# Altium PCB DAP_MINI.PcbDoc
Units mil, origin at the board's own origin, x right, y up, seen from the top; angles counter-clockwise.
Board outline 1574.69 x 695 mil, 2 copper layers (Top Layer, Bottom Layer), stack 61.756 mil thick; 34 components, 48 nets, 171 pads, 93 vias.
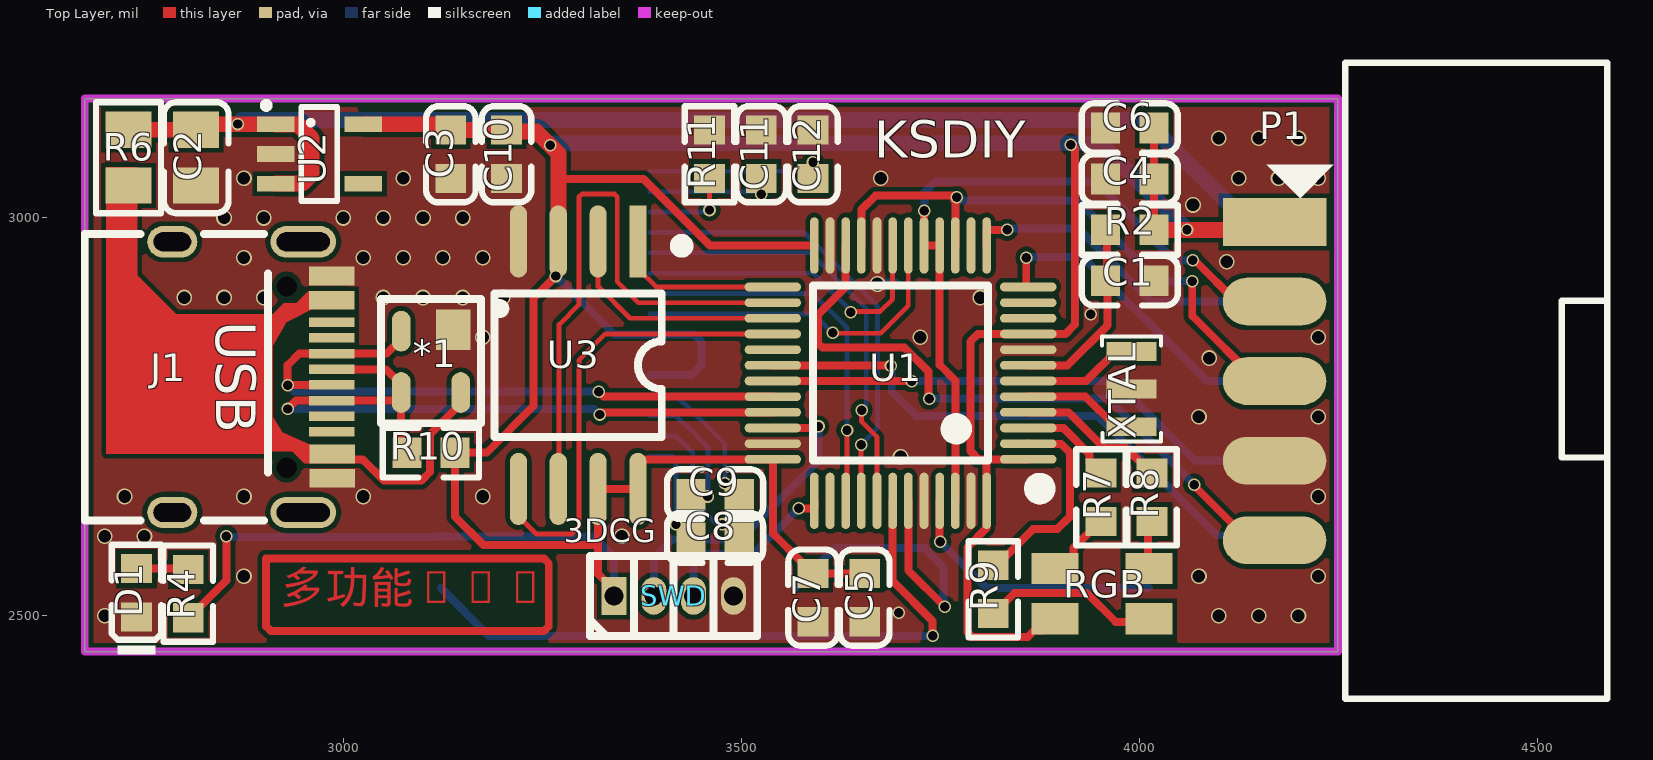
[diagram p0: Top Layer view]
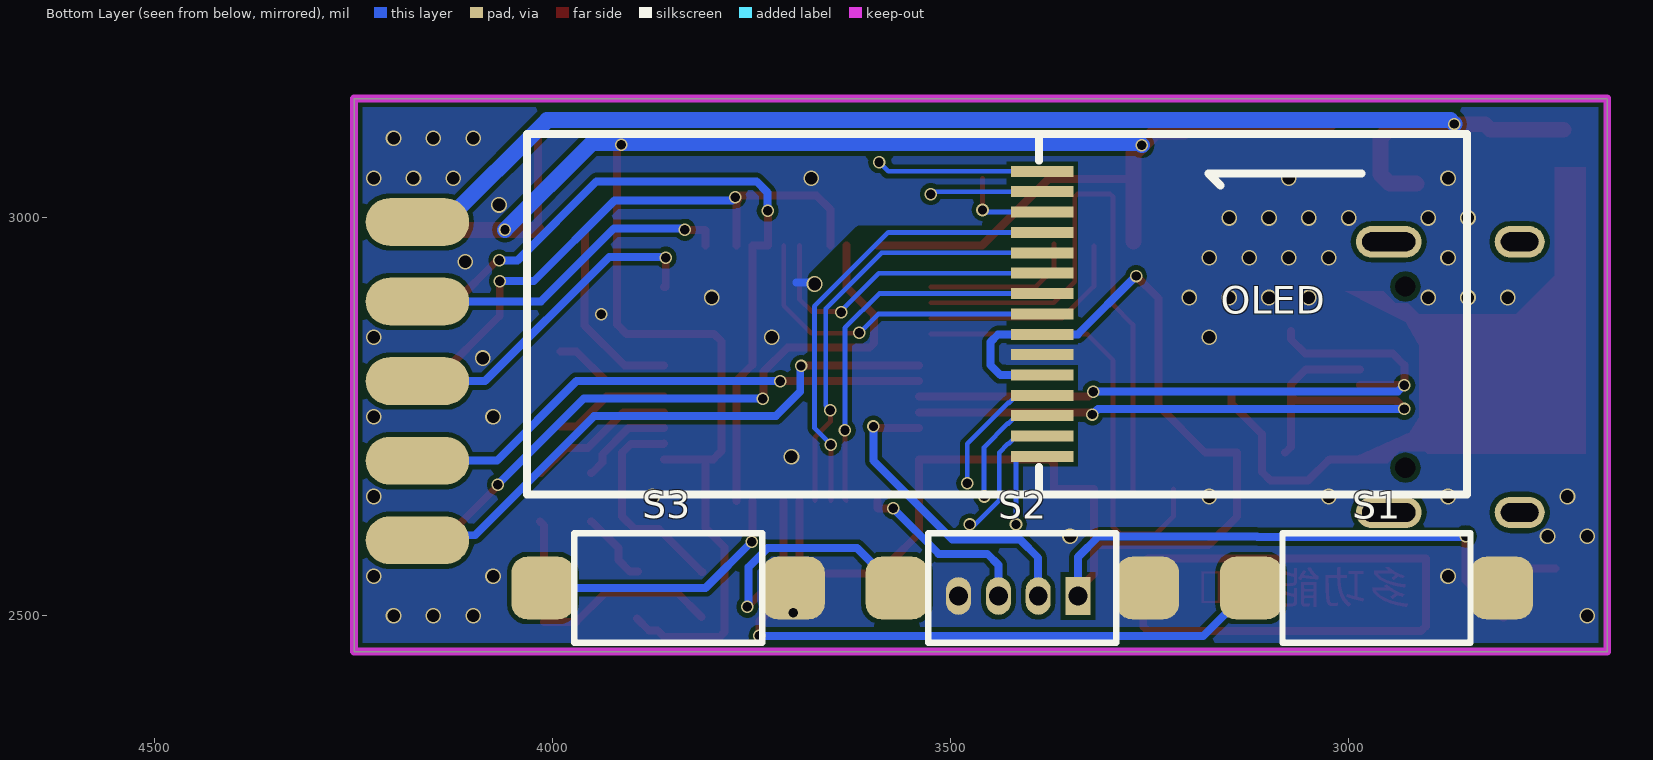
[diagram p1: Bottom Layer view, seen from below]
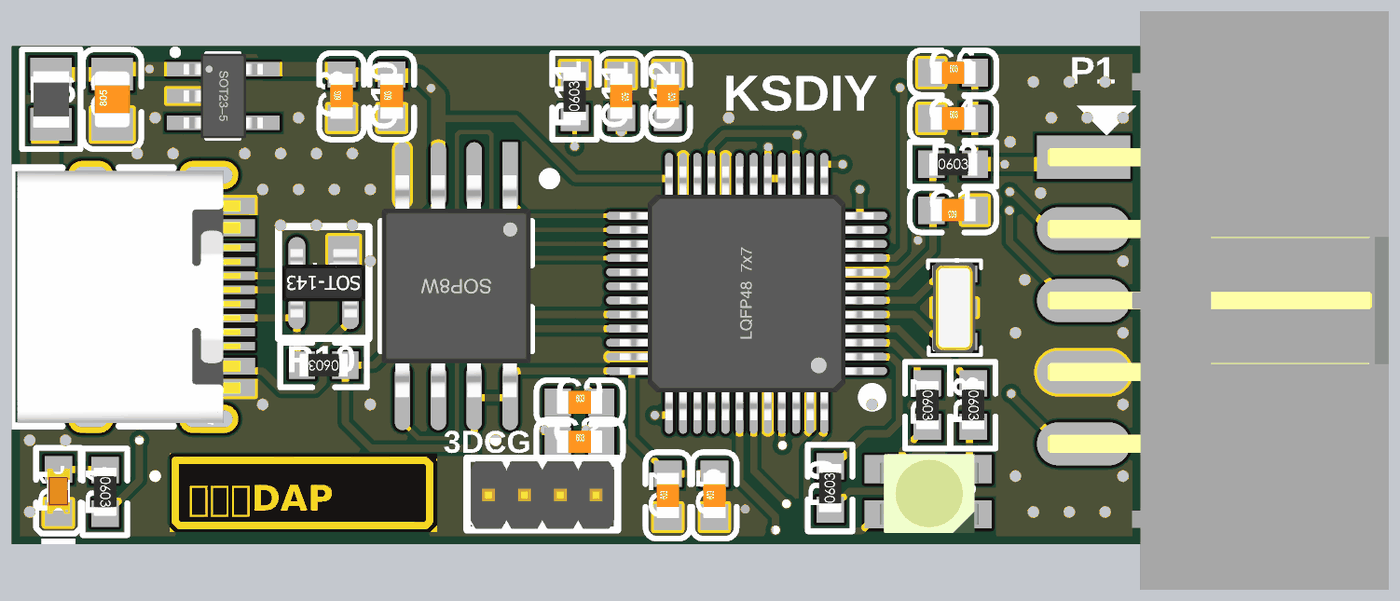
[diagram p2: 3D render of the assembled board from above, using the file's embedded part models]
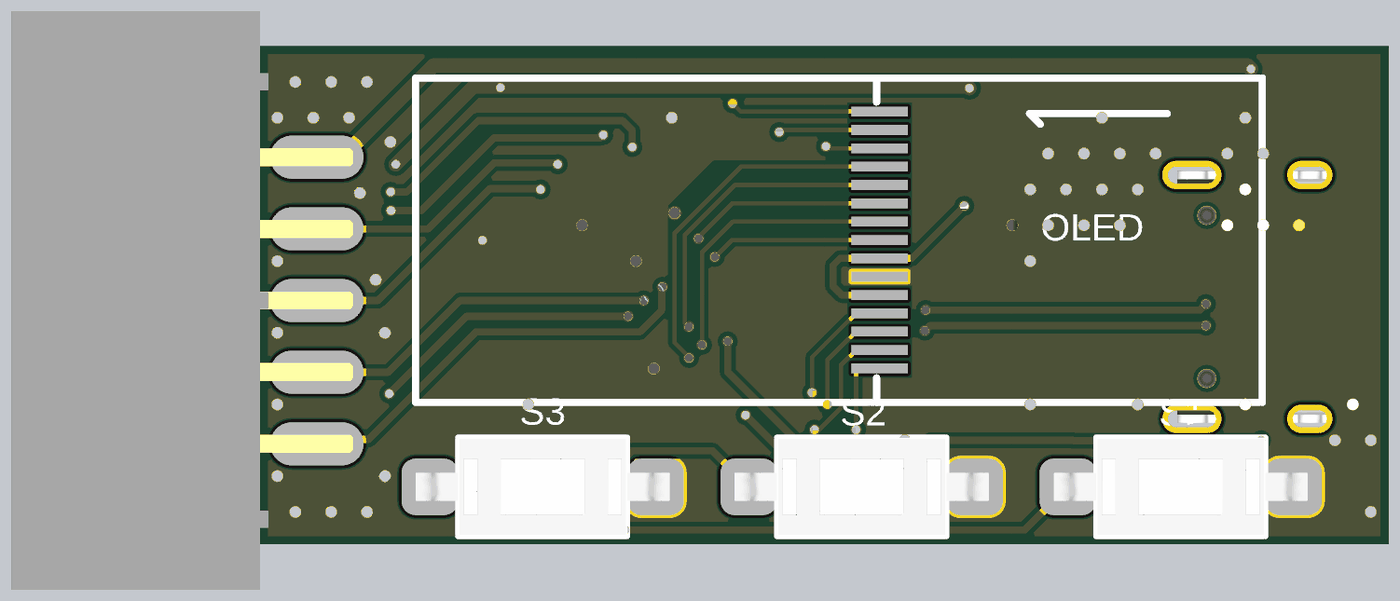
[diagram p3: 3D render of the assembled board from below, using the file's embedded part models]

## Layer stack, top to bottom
Top Solder: solder mask 1, SM-001, Dk 4
Top Layer: signal copper 1.378
Dielectric 1: core 59, Core-043, Dk 4.3
Bottom Layer: signal copper 1.378
Bottom Solder: solder mask 1, SM-001, Dk 4

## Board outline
2675,2455 2675,3150 4249.69,3150 4249.69,2455

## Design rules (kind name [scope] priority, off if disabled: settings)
Clearance [All] p1: gap=6 ignorepadtopadclearanceinfootprint=FALSE
PolygonConnect [All] p1: connectstyle=Direct reliefconductorwidth=10 reliefentries=4 polygonreliefangle="90 Angle" airgapwidth=10
RoutingVias [All] p1: holewidth=11.81 width=15.75 viastyle="Through Hole" minholewidth=11.81 minwidth=15.75 maxholewidth=11.81 maxwidth=15.75
SolderMaskExpansion [All] p1: expansion=4 istentingtop=FALSE
Width [InNet('No Net')] p1: maxlimit=20 minlimit=6 preferedwidth=6
30 further rules are at their usual default settings.

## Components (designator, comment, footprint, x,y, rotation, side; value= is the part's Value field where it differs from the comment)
*1 "PRTR5V0U2X" LC-SOT-143 3110,2820 r90 top
C1 "106" 0603_C 3988,2921 r180 top
C2 "106" 0805_C 2815,3075.75 r90 top
C3 "106" 0603_C 3135,3080 r90 top value=104
C4 "106" 0603_C 3988,3049 r0 top value=104
C5 "106" 0603_C 3655,2523 r90 top value=104
C6 "106" 0603_C 3988,3113 r0 top value=104
C7 "106" 0603_C 3590,2523 r90 top value=104
C8 "106" 0603_C 3467,2598 r0 top value=104
C9 "106" 0603_C 3467,2653 r0 top value=104
C10 "106" 0603_C 3205,3080 r90 top
C11 "106" 0603_C 3525,3080 r270 top value=104
C12 "106" 0603_C 3590,3080 r270 top value=104
D1 "白灯 0603" 0603_LED_S1 2740,2529 r90 top
J1 "USB type C" "USB Type-C-16Pin_A" 2785,2800 r270 top
OLED "QG-2832TLBFG02" 0.91-OLED 4031.57,3156.38 r180 bottom (schematic designator OLED1)
P1 "Header 5X2" "300S-2*5P 2.54MM_2" 4170,2995 r0 top
R2 "Res2" 0603_R 3988,2985 r0 top value=10K
R4 "Res2" 0603_R 2805,2528 r270 top value=1K
R6 "1A保险丝" 0805_L 2730,3075.75 r270 top value=1000MA
R7 "1K" 0603_R 3952,2649 r270 top value=300R
R8 "1K" 0603_R 4016,2649 r270 top value=300R
R9 "1K" 0603_R 3816.46,2533.36 r90 top value=300R
R10 "Res2" LC-0603_R 3110,2705 r180 top value=1.5K
R11 "Res2" 0603_R 3460,3080 r90 top value=10K
RGB "RGB_LED" LED_3528_RGB 3953.02,2528.08 r180 top (schematic designator RGB1)
S1 "RST" KEY 2965,2535 r0 bottom
S2 "RST" KEY 3410,2535 r0 bottom
S3 "RST" KEY 3855,2535 r0 bottom
SWD "Header 4" HDR1.27-LI-4P 3415,2525 r0 top (schematic designator SWD1)
U1 "STM32F103C" "LQFP48 7X7_N" 3700,2805 r90 top
U2 "MIC5219" SOT23-5N 2970,3080.37 r270 top
U3 "W25QXX" SOP8W_N 3295,2815 r270 top
XTAL "8M" XTAL-3215-3P 3990,2785 r90 top (schematic designator XTAL1)

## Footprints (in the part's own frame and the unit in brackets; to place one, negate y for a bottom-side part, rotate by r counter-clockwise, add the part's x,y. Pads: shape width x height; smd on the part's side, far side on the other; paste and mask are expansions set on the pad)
0.91-OLED [mm]
  rect 2x0.35 smd: 1(16.423,-11.585) 2(16.423,-10.933) 3(16.423,-10.283) 4(16.423,-9.633) 5(16.423,-8.985) 6(16.423,-8.335) 7(16.423,-7.685) 8(16.423,-7.035) 9(16.423,-6.385) 10(16.423,-5.735) 11(16.423,-5.085) 12(16.423,-4.435) 13(16.423,-3.785) 14(16.423,-3.135) 15(16.423,-2.485)
  silkscreen extent -0.02,-12.79 29.98,-1.29
"300S-2*5P 2.54MM_2" [mil] "2.54mm 2*5P 直 简牛"
  rect 130x60 smd: 1(0,0)
  oval 130x60 smd far side: 2(0,0) 4(0,-100) 6(0,-200) 8(0,-300) 10(0,-400)
  oval 130x60 smd: 3(0,-100) 5(0,-200) 7(0,-300) 9(0,-400)
  silkscreen extent -10,-599 418,200, body extent -50,-604 426,204, height 169
0603_C [mm]
  rect 0.93x0.98 smd: 1(-0.77,0) 2(0.77,0)
  silkscreen extent -1.53,-0.79 1.54,0.79, body extent -0.8,-0.4 0.8,0.4, height 0.3
0603_LED_S1 [mm]
  rect 0.93x0.98 smd: A(0.77,0) K(-0.77,0)
  silkscreen extent -1.98,-0.79 1.54,0.79, body extent -0.8,-0.4 0.8,0.4, height 0.6
0603_R [mm]
  rect 0.93x0.98 smd: 1(-0.77,0) 2(0.77,0)
  silkscreen extent -1.53,-0.79 1.54,0.79, body extent -0.85,-0.4 0.85,0.4, height 0.56
0805_C [mm]
  rect 1.16x1.47 smd: 1(-0.89,0) 2(0.89,0)
  silkscreen extent -1.77,-1.04 1.77,1.04, body extent -1,-0.62 1,0.63, height 0.77
0805_L [mm]
  rect 1.16x1.47 smd: 1(-0.89,0) 2(0.89,0)
  silkscreen extent -1.77,-1.04 1.77,1.03, body extent -1.02,-0.64 1.03,0.64, height 0.6
HDR1.27-LI-4P [mm] "直插，脚距：1.27mm"
  rect 0.8x1.2 hole 0.6: 1(-1.905,0)
  oval 0.8x1.2 hole 0.6: 2(-0.635,0) 3(0.635,0) 4(1.905,0)
  silkscreen extent -2.67,-1.27 2.67,1.27, body extent -2.54,-1.24 2.54,1.16, height 4.48
KEY [mm]
  rrect50% 2x2 smd: 1(-4,0) 2(4,0)
  silkscreen extent -3,-1.75 3,1.75, body extent -4.5,-1.75 4.5,1.75, height 4.5
LC-0603_R [mm]
  rect 0.93x0.98 smd: 1(-0.77,0) 2(0.77,0)
  silkscreen extent -1.53,-0.79 1.54,0.79, body extent -0.85,-0.4 0.85,0.4, height 0.56
LC-SOT-143 [mm]
  rect 1.3x1.1 smd: 1(1,-0.71)
  oval 1.3x0.6 smd: 2(0.96,0.95) 3(-1,0.95) 4(-1,-0.95)
  silkscreen extent -1.98,-2.35 1.98,1.6, body extent -1.23,-1.46 1.19,1.46, height 1
LED_3528_RGB [mm]
  rect 1.5x1 smd: 1(1.5,-0.8) 2(-1.5,-0.8) 3(-1.5,0.8) 4(1.5,0.8)
  body extent -1.79,-1.34 1.71,1.46, height 1.9
"LQFP48 7X7_N" [mm] "48脚，体宽7x7mm，脚距0.5mm"
  oval 0.279x1.8 smd: 1(-2.75,-4.075) 2(-2.25,-4.075) 3(-1.75,-4.075) 4(-1.25,-4.075) 5(-0.75,-4.075) 6(-0.25,-4.075) 7(0.25,-4.075) 8(0.75,-4.075) 9(1.25,-4.075) 10(1.75,-4.075) 11(2.25,-4.075) 12(2.75,-4.075) 25(2.75,4.075) 26(2.25,4.075) 27(1.75,4.075) 28(1.25,4.075) 29(0.75,4.075) 30(0.25,4.075) 31(-0.25,4.075) 32(-0.75,4.075) 33(-1.25,4.075) 34(-1.75,4.075) 35(-2.25,4.075) 36(-2.75,4.075)
  oval 1.8x0.279 smd: 13(4.075,-2.75) 14(4.075,-2.25) 15(4.075,-1.75) 16(4.075,-1.25) 17(4.075,-0.75) 18(4.075,-0.25) 19(4.075,0.25) 20(4.075,0.75) 21(4.075,1.25) 22(4.075,1.75) 23(4.075,2.25) 24(4.075,2.75) 37(-4.075,2.75) 38(-4.075,2.25) 39(-4.075,1.75) 40(-4.075,1.25) 41(-4.075,0.75) 42(-4.075,0.25) 43(-4.075,-0.25) 44(-4.075,-0.75) 45(-4.075,-1.25) 46(-4.075,-1.75) 47(-4.075,-2.25) 48(-4.075,-2.75)
  silkscreen extent -3.93,-4.69 2.79,2.79, body extent -4.5,-4.5 4.5,4.5, height 1.45
SOP8W_N [mm] "5.3*8.3*1.8mm（长宽高）"
  rect 2.3x0.55 smd: 1(-3.95,1.905)
  oval 2.3x0.55 smd: 2(-3.95,0.635) 3(-3.95,-0.635) 4(-3.95,-1.905) 5(3.95,-1.905) 6(3.95,-0.635) 7(3.95,0.635) 8(3.95,1.905)
  silkscreen extent -3.94,-2.67 2.29,3.43, body extent -3.94,-2.64 3.94,2.64, height 1.9
SOT23-5N [mm] "3x1.6x1.1mm(长宽高)"
  rect 0.5x1.2 smd: 1(-0.95,-1.4) 2(0,-1.4) 3(0.95,-1.4) 4(0.95,1.4) 5(-0.95,1.4)
  silkscreen extent -1.63,-1.78 1.5,0.56, body extent -1.5,-1.4 1.5,1.4, height 1.15
"USB Type-C-16Pin_A" [mm]
  round 0 hole 0.65: 0(-2.89,3.65) 0(2.89,3.65)
  oval 1x2.1 hole 0.6 slot 1.7 at 90 deg: 1(-4.32,4.18) 1(4.32,4.18)
  oval 1x1.6 hole 0.6 slot 1.2 at 90 deg: 1(-4.32,0) 1(4.32,0)
  rect 0.3x1.45 smd: A1(-3.375,5.092) A4(-2.6,5.092) A5(-1.25,5.092) A6(-0.25,5.092) A7(0.25,5.092) A8(-1.75,5.092) A9(2.6,5.1) A12(3.375,5.1) B1(3.075,5.1) B4(2.3,5.1) B5(1.75,5.092) B6(0.75,5.092) B7(-0.75,5.092) B8(1.25,5.092) B9(-2.3,5.092) B12(-3.075,5.092)
  silkscreen extent -4.57,-2.79 4.57,3.05, body extent -4.47,-2.6 4.47,5.3, height 3.25
XTAL-3215-3P [mm]
  rect 0.6x1.6 smd: 1(-1.2,0) 2(0,0) 3(1.2,0)
  silkscreen extent -1.68,-0.94 1.68,0.94, body extent -1.6,-0.74 1.6,0.76, height 0.9

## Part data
C1 C2 C3 C4 C5 C6 C7 C8 C9 C10 C11 C12: library part C_1
D1: library part "0603 白灯", "发光二极管", Package=0603, SuppliersPartNumber=C2290
J1: library part USB_C
OLED: library part 0.91-OLED, BOM_Manufacturer=Allvision
P1: "Header, 5-Pin, Dual row"
R2 R4 R10 R11: "Resistor"
R6 R7 R8 R9: library part Res2, "Resistor"
RGB: "三色高亮LED"
S1 S2 S3: library part SW-PB, "Switch"
SWD: "Header, 4-Pin"
U2: "3.3V 降压芯片"
U3: "SPI FLASH"
XTAL: library part XTAL1

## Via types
v1: diameter 19.68, hole 15.75, Top Layer to Bottom Layer, tented both sides, 54 vias
v2: diameter 15.75, hole 11.81, Top Layer to Bottom Layer, tented both sides, 39 vias

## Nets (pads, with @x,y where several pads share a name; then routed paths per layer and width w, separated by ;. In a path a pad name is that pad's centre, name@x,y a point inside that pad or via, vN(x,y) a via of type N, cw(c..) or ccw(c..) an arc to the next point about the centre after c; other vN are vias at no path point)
3V3: C3.2 C4.2 C5.2 C6.2 C7.2 C10.2 OLED.5 OLED.7 P1.1 R2.2 R4.2 R10.1 RGB.4 SWD.1 U1.1 U1.9 U1.24 U1.36 U1.48 U2.5 U3.3 U3.7 U3.8 | length 4973.6
  Top Layer w10: R4.2 2805.98,2497.68 2853,2544.7 v2(2853,2600) ; v2(3267,2927) 3239,2899 3239,2764 3180,2705 R10.1 3140.31,2624.69 3176.11,2588.89 3320,2588.89 ; 3270,3050 3271,3049 3377,3049 3460.55,2965.45 U1.24 ; SWD.1 3340,2532.87 3320,2552.88 3320,2588.89 ; C5.2 C7.2 3589.02,2553.32 3575.71,2566.62 3575.71,2567.61 3539.55,2603.76 U1.36 3375.95,2696.73 3370,2690.78 U3.8 U3.7 3320,2588.89 ; U1.1 3809,2696.73 ; RGB.4 3879.28,2481.9 3868.23,2481.9 3860.07,2473.74 3789.86,2473.74 3784,2479.6 3784,2586.21 3808.08,2610.29 3808.08,2644.36 U1.48 3808.27,2696 3809,2696.73 ; v2(3914,3092) 3919,3087 3919,2866 3907.21,2854.21 U1.9 3797.21,2854.21 3788,2845 3788,2707 3798.27,2696.73 3809,2696.73 ; C6.2 C4.2 4018.32,2987 R2.2@4020.32,2985
  Top Layer w20: U2.5 3113.42,3117.77 3120.87,3110.32 C3.2 C10.2 3206.82,3108.5 3242.58,3108.5 3270,3081.07 3270,3050 U3.3 ; R2.2@4020.32,2985 v2(4060,2985) 4160,2985 P1.1
  Bottom Layer w10: v2(2853,2600) 2853.76,2599.24 3114.22,2599.24 3114.98,2600 3314,2600 3340,2574 SWD.1 ; v2(3267,2927) 3340.18,2853.82 OLED.7 3440.32,2853.82 3450,2844.14 3450,2815 3437.64,2802.64 OLED.5
  Bottom Layer w20: v2(3259.73,3091.32) 3262.29,3093.87 3951.13,3093.87 v2(4060,2985)
5V: C2.2 P1.2 R6.1 U2.1 U2.3 | length 1693.4
  Top Layer w20: R6.1 2821.69,3110.79 2828.67,3117.77 U2.1 2915.04,3117.61 2942.39,3117.61 2960,3100 2960,3055 2948.13,3043.13 2915.04,3043.13 U2.3
  Bottom Layer w20: v2(2867,3118) 2872,3123 4007,3123 4135,2995 P1.2
5V_IN: *1.4 J1.A4 J1.A9 J1.B4 J1.B9 R6.2 | length 254.8
  Top Layer w10: J1.A9 2986.69,2696.73 3023.27,2696.73 3024,2696 3025,2696 3051,2670 3098,2670 3109,2681 3109,2728.45 3147.4,2766.85 *1.4
CLK: SWD.3 U1.37 | length 229.4
  Top Layer w10: v2(3572,2635) 3591.27,2635 3591.73,2635.46 U1.37
  Bottom Layer w10: SWD.3 3440,2564 3454,2578 3515,2578 v2(3572,2635)
DIO: SWD.2 U1.34 | length 406.8
  Top Layer w10: U1.34 3593.55,2736.1 3595.44,2738 v2(3597,2738)
  Bottom Layer w10: SWD.2 3390,2573 3413,2596 3498,2596 3597,2695 v2(3597,2738)
GND: *1.1 C1.1 C2.1 C3.1 C4.1 C5.1 C6.1 C7.1 C10.1 C11.1 C12.1 D1.K J1.A1 J1.A12 J1.B1 J1.B12 OLED.6 P1.7 R11.2 S1.1 S2.1 S3.1 SWD.4 U1.8 U1.20 U1.23 U1.35 U1.44 U1.47 U2.2 U3.4 XTAL.2 | length 23.8
  Bottom Layer w10: v1(3671,2917) 3672.85,2918.85 3693.85,2918.85 3694,2919
  other v1: 2700,2500 4100,2500 4150,2500 4200,2500 2875,2550 4075,2550 4225,2550 2700,2600 2750,2600 3350,2600 2725,2650 2875,2650 3025,2650 3175,2650 3875,2650 4225,2650 3700,2700 4075,2750 4225,2750 4088,2824 3175,2850 3725,2850 4225,2850 2800,2900 2850,2900 2900,2900 3050,2900 3100,2900 3150,2900 3200,2900 3800,2900 4110,2945 2875,2950 3025,2950 3075,2950 3125,2950 3175,2950 2850,3000 2900,3000 3000,3000 3050,3000 3100,3000 3150,3000 4067.5,3016.32 2875,3050 3075,3050 3675,3050 4125,3050 4175,3050 4225,3050 4100,3100 4150,3100 4200,3100
  other v2: 3698,2504 3939,2879
KEY1: S1.2 U1.42 | length 833.2
  Top Layer w10: U1.42 3690.16,2543.84 3740.27,2493.73 v2(3740.27,2474.85)
  Bottom Layer w10: S1.2 3182.63,2474.85 v2(3740.27,2474.85)
KEY2: S2.2 U1.43 | length 419.9
  Top Layer w10: U1.43 3709.84,2557.07 v2(3755.5,2511.42)
  Bottom Layer w10: S2.2 3617.85,2585.37 3729.91,2585.37 3754.13,2561.16 3754.13,2512.79 v2(3755.5,2511.42)
KEY3: S3.2 U1.45 | length 338.4
  Top Layer w10: U1.45 3749.21,2593.79 v2(3749.96,2593.04)
  Bottom Layer w10: v2(3749.96,2593.04) 3808,2535 S3.2
LCD_CS: OLED.8 U1.18 | length 425
  Top Layer w6: v2(3615,2855.87) 3615.87,2855 3675,2855 3709.84,2889.84 U1.18
  Bottom Layer w6: OLED.8 3590.59,2879.41 3614.13,2855.87 v2(3615,2855.87)
LCD_D0: OLED.11 U1.41 | length 552.9
  Top Layer w6: v2(3651.13,2758.49) 3651.13,2743.87 3670.47,2724.53 U1.41
  Bottom Layer w6: OLED.11 3586.84,2956.19 3656.87,2886.16 3656.87,2764.24 v2(3651.13,2758.49)
LCD_D1: OLED.12 U1.40 | length 577.7
  Top Layer w6: U1.40 3650.39,2644.95 3650.39,2714.35 v2(3650.85,2714.8)
  Bottom Layer w6: OLED.12 3578.22,2981.78 3671.13,2888.87 3671.13,2736.13 3650.85,2715.85 v2(3650.85,2714.8)
LCD_DC: OLED.10 U1.19 | length 400.6
  Top Layer w6: v2(3637.53,2881.64) 3638.36,2882.47 3674.58,2882.47 3690,2897.89 3690,2965.29 U1.19
  Bottom Layer w6: OLED.10 3590.24,2930.59 3637.53,2883.3 v2(3637.53,2881.64)
LCD_RES: OLED.9 U1.39 | length 483.7
  Top Layer w6: U1.39 3632.81,2646.26 v2(3632.81,2733.19)
  Bottom Layer w6: OLED.9 3589.74,2905 3632.81,2861.93 v2(3632.81,2733.19)
"LED G": R8.1 U1.4 | length 187.2
  Top Layer w10: U1.4 3911.21,2755.79 3956,2711 3983.33,2711 4015.02,2679.31 R8.1
"LED R": R7.1 U1.3 | length 121.1
  Top Layer w10: U1.3 3860.64,2735.91 3904.72,2735.91 3937.71,2702.92 3937.71,2692.62 3951.02,2679.31 R7.1
LED_DAP: R9.2 U1.2 | length 267.1
  Top Layer w10: R9.2@3812,2555.32 3812.98,2555.32 3866.67,2609 3897,2609 3913,2625 3913,2705 3901.77,2716.23 3860.64,2716.23 U1.2
NetC8_1: C8.1 OLED.1 | length 116
  Bottom Layer w6: OLED.1 3413.99,2700.28 3417.88,2696.39 v2(3417.88,2614.87)
NetC8_2: C8.2 OLED.2 | length 172.7
  Bottom Layer w6: OLED.2 3417.48,2725.95 3427.26,2716.17 3428.1,2716.17 3439,2705.27 3439,2645.14 3470.06,2614.08 3475.03,2614.08 v2(3475.83,2614.87)
NetC9_1: C9.1 OLED.3 | length 151.3
  Bottom Layer w6: OLED.3 3417.48,2751.54 3427.18,2741.84 3428.1,2741.84 3458,2711.94 v2(3458,2650)
NetC9_2: C9.2 OLED.4 | length 169.3
  Bottom Layer w6: OLED.4 3417.48,2777.13 3427.18,2767.43 3428.1,2767.43 3479.22,2716.31 v2(3479.22,2666.42)
NetC11_2: C11.2 OLED.14 | length 141.2
  Bottom Layer w6: OLED.14 3522.04,3032.96 v2(3525,3030)
NetC12_2: C12.2 OLED.15 | length 209.7
  Bottom Layer w6: OLED.15 3578.55,3058.55 v2(3590,3070)
NetD1_A: D1.A R4.1 | length 65.4
  Top Layer w10: D1.A 2804,2559.32 R4.1
NetOLED1_13: OLED.13 R11.1 | length 115.8
  Top Layer w6: v2(3460,3010) R11.1
  Bottom Layer w6: OLED.13 3457.37,3007.37 v2(3460,3010)
NetR7_2: R7.2 RGB.1 | length 94
  Top Layer w10: RGB.1@3892.94,2555.5 3902.79,2555.5 3917.47,2570.18 3917.47,2585.14 3951.02,2618.68 R7.2
NetR8_2: R8.2 RGB.2 | length 65.2
  Top Layer w10: RGB.2@4011.06,2555.5 4011.06,2613.74 R8.2
NetR9_1: R9.1 RGB.3 | length 225.8
  Top Layer w10: R9.1@3812.98,2498.59 3843.42,2529.03 3859.74,2529.03 3859.88,2528.89 3933.92,2528.89 3970.3,2492.5 RGB.3@4011.06,2492.5
NRF_CE: U1.29
NRF_CSN: U1.14
NRF_MISO: P1.3 U1.16 U1.17 U1.46 | length 923.8
  Top Layer w10: v2(3730,3009.13) 3729.72,3008.84 3729.72,2965.64 U1.17 U1.16 3749.21,2815.41 3768.9,2795.73 U1.46 ; v2(4067.12,2946.61) 4068.22,2945.51 4070.96,2945.51 4121.47,2895 P1.3
  Bottom Layer w10: v2(3730,3009.13) 3730,3032 3744,3046 3945,3046 4044.39,2946.61 v2(4067.12,2946.61)
NRF_SCK: P1.5 U1.15 U1.21 | length 756.2
  Top Layer w10: U1.21 3650.98,2965.64 3650.98,3010.49 3668.49,3028 3768.55,3028 v2(3770.56,3025.99) 3767,3022.44 3768.9,3020.55 U1.15 ; v2(4066.54,2920.56) 4066.54,2876.99 4148.53,2795 P1.5
  Bottom Layer w10: v2(3770.56,3025.99) 3774.55,3022 3922.41,3022 4023.85,2920.56 v2(4066.54,2920.56)
OSC1: U1.5 XTAL.1 | length 145.2
  Top Layer w10: U1.5 3932.6,2775.47 3970.31,2737.76 XTAL.1
OSC2: U1.6 XTAL.3 | length 144.9
  Top Layer w10: U1.6 3933.23,2795.16 3970.31,2832.24 XTAL.3
RST: C1.2 R2.1 U1.7 | length 240.5
  Top Layer w10: U1.7 3909.84,2814.84 3960,2865 3960,2910 3959.69,2910.31 R2.1@3959.69,2985
SPI2_MISO: U1.27 U3.2 | length 272.2
  Top Layer w6: U3.2@3320,2965.03 3320,2914 3360.1,2873.9 U1.27@3524.55,2873.9
SPI2_MOSI: U1.28 U3.5 | length 574.8
  Top Layer w6: U3.5 3220,2625.04 3242.15,2602.89 3287.07,2602.89 3296,2611.82 3296,2821 3329.21,2854.21 U1.28@3524.55,2854.21
SPI2_SCK: U1.26 U3.6 | length 727.5
  Top Layer w6: U3.6@3271,2658.26 3271,2866 3296,2891 3296,3026.49 3299.51,3030 3340.49,3030 3344,3026.49 3344,2920 3370.42,2893.58 U1.26@3524.55,2893.58
TDI: U1.10
TDO: U1.11
TRST: P1.9 U1.22 | length 833.9
  Top Layer w10: U1.22 3631.1,2913.1 3596.13,2878.13 3596.13,2842.86 3601.98,2837 3705,2837 3735,2807 3735,2774 v2(3736,2773) ; v2(4069,2665) 4069,2663.44 4137.44,2595 P1.9
  Bottom Layer w10: v2(3736,2773) 3961,2773 v2(4069,2665)
USART1_RX: P1.8 U1.31 | length 671.9
  Top Layer w10: U1.31 3539.71,2795 v2(3714,2795)
  Bottom Layer w10: v2(3714,2795) 3970,2795 4070,2695 P1.8
USART1_TX: P1.10 U1.30 | length 739.8
  Top Layer w10: U1.30 3687.16,2814.84 v2(3688,2814)
  Bottom Layer w10: v2(3688,2814) 3689,2813 3689,2781.8 3719.67,2751.14 3947.86,2751.14 4097.68,2601.32 4163.68,2601.32 P1.10
USART2_RX: P1.4 U1.13 | length 419.9
  Top Layer w10: U1.13 3808.27,2984.54 3808.73,2985 v2(3834,2985)
  Bottom Layer w10: v2(3834,2985) 3836,2987 3923,2987 4015,2895 P1.4
USART2_TX: P1.6 U1.12 | length 415.9
  Top Layer w10: v2(3858,2950) 3858,2913.73 3858.46,2913.27 U1.12
  Bottom Layer w10: v2(3858,2950) 3859,2951 3929,2951 4085,2795 P1.6
USB_DM: *1.2 J1.A7 J1.B7 U1.32 | length 862.3
  Top Layer w10: J1.A7 2985.38,2790.08 2930.08,2790.08 v2(2930,2790) 2930,2815 2944.53,2829.53 J1.B7 3054.43,2829.53 3072.6,2847.7 *1.2 ; v2(3320.69,2781.82) 3327.03,2775.47 U1.32
  Bottom Layer w10: v2(2930,2790) 2938.18,2781.82 v2(3320.69,2781.82)
USB_DP: *1.3 J1.A6 J1.B6 R10.2 U1.33 | length 946.9
  Top Layer w10: v2(2930,2760) 2940.48,2770.48 J1.B6 3066.31,2770.48 *1.3@3072.6,2776.77 ; J1.A6 3053.47,2809.85 3072.6,2790.72 *1.3 *1.3@3072.6,2776.77 ; R10.2 3072.6,2712.09 *1.3@3072.6,2776.77 ; v2(3321.96,2752.99) 3323.51,2752.99 3326.31,2755.79 U1.33
  Bottom Layer w10: v2(2930,2760) 3314.95,2760 v2(3321.96,2752.99)
W25Q_CS: U1.25 U3.1 | length 195.3
  Top Layer w6: U3.1@3370,2967.4 3370,2936.06 3392.8,2913.27 U1.25@3524.55,2913.27
pads on no net: J1.0 J1.1 J1.A5 J1.A8 J1.B5 J1.B8 U1.38 U2.4
copper on no net: | length 879.7
  Top Layer w10: 2903,2572 2903,2520 2903,2486.86 2908.86,2481 3252.14,2481 3258,2486.86 3258,2566.14 3252.14,2572 2905,2572

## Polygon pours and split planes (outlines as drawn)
GND on Top Layer "GND_L01_P000" (solid, pour order 0): 2675,3153 4252,3153 4252,2453 4251,2452 4245.5,2457.5 2675,2457.5 2675,3151 2674,3152
GND on Bottom Layer "GND_L02_P001" (solid, pour order 1): 2674,3152 2676,3150 4248,3150 4248,2452 4242.5,2457.5 2675,2457.5 2675,3152

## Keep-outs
Keep-Out Layer:
  lines w10: 2675,2455 2675,2460 2675,3150 4249.69,3150 4249.69,2455 2675,2455

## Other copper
Top Layer:
  region net 5V_IN: 2702,3064 2702,2704 2901,2704 2911,2714 2911,2879 2790,2879 2741,2928 2741,3064
  region net 5V_IN: 2922.95,2731.02 2902,2765 2847,2765 2847,2707 2916,2707 2936,2707 2951,2692 3010,2692
  region net 5V_IN: 2927.95,2868.98 2907.95,2834 2853,2834 2853,2865 2897,2865 2925,2893 2941,2893 2956,2908 3005,2908
  text "多功能DAP" at 2921,2502 h70

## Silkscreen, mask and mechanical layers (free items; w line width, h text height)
Top Overlay:
  text "KSDIY" at 3667,3059.96 h80
  text "3DCG" at 3277,2582.6 h50
Top Solder:
  rectangle: 2895,2472 3268.27,2581.56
